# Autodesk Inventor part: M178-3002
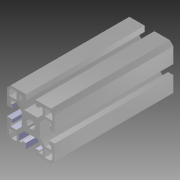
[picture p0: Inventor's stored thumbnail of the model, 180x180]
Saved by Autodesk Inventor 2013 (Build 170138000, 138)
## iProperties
Created: 2004-10
Material: Aluminium - 6061
Document SubType Name: Modeling
Designer: Autodesk, Inc.
Manufacturer: Standard
Standards Organization: Custom
Description: HUTCH, CROSS BAR
Stock Number: 10-040
Catalog Web Link: http://www.parker.com/ead/cm1.asp?cmid=809
Vendor: PARKER IPS
Part Number: M178-3002
Mass: 179.948 g
Surface Area: 483.565 cm^2
Volume: 66.4013 cm^3
Density: 2.71 g/cm^3
CAGE: 1LJX3
Dept. ID: Product Design
Description #2: ---
Finish #1: ---
Finish #2: ---
Material ID: ---
Project Number: ---
Length: 1828.800 mm
Author: Autodesk, Inc.
Revision Number: A
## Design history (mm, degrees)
derived "40 Series Profiles.ipt"
body "Solid1"
tag "TaggingFeature2"
feature "Solid1::40 Series Profiles.ipt" dims "ScaleForDerivedMember" = 10
other parameters: "Length" = 1828.8
